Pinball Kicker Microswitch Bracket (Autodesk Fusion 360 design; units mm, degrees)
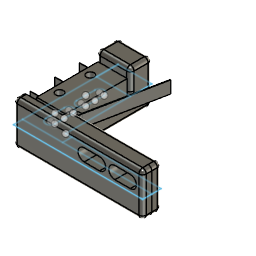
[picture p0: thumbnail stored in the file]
sketch "Microswitch" plane through (0, 0, 0) normal (0, 0, 1) x axis (1, 0, 0)
  line L1 (-2.5, -5) -> (7, -5)
  line L2 (-2.5, 15) -> (-2.5, -5)
  line L3 (7, 15) -> (-2.5, 15)
  line L4 (13, 23) -> (8.2, -1)
  line L5 (-6.5, -3) -> (-2.5, -3)
  line L6 (-6.5, 13) -> (-2.5, 13)
  line L7 (-6.5, 5) -> (-2.5, 5)
  line L8 (13.2, 23) -> (8.2, -2)
  line L9 (13.2, 23) -> (13, 23)
  line L10 (8.2, -2) -> (8, -2)
  line L11 (-6.5, -3.1) -> (-2.5, -3.1)
  line L12 (-6.5, 4.9) -> (-2.5, 4.9)
  line L13 (-6.5, 12.9) -> (-2.5, 12.9)
  line L14 (-6.5, 12.9) -> (-6.5, 13)
  line L15 (-6.5, 4.9) -> (-6.5, 5)
  line L16 (-6.5, -3.1) -> (-6.5, -3)
  line L17 (7, -5) -> (7, 15)
  line L18 (8.2, -1) -> (7, -1)
  line L19 (7, -2) -> (8.2, -2)
  circle C1 centre (0, 0) radius 1.25
  circle C2 centre (0, 10) radius 1.25
  point P1 (0, 0)
  point P2 (0, 0)
  point P8 (-2.5, -3)
  point P10 (-2.5, 13)
  point P12 (-2.5, 5)
  point P24 (7, -1)
  point P26 (7, -2)
  coincident P1 P2
  horizontal L1
  perpendicular L1 L2
  perpendicular L2 L3
  coincident L2 P8
  perpendicular L2 L5
  coincident L2 P10
  perpendicular L2 L6
  midpoint L2 P12
  perpendicular L2 L7
  horizontal L9
  perpendicular L13 L14
  perpendicular L12 L15
  perpendicular L11 L16
  coincident L17 P24
  coincident L17 P26
  perpendicular L17 L19
extrude "Extrude1" new body sketch "Microswitch" profile of C1 C2 L1 L2 L3 along normal blind 6.5 bodies "Microswitch"
extrude "Extrude3" add sketch "Microswitch" profile of L2 L5 L6 L7 L11 L12 L13 L14 L15 L16 blind 4 from offset 1.25
sketch "Game Deck Geometry" plane through (0, 0, 0) normal (0, 0, 1) x axis (1, 0, 0)
  line L1 (38, 5) -> (11, 5)
  line L2 (38, -4) -> (15, -4)
  line L3 (11, -4) -> (11, 5)
  line L4 (15, -4) -> (11, -4)
  line L5 (38, 5) -> (38, -4)
  circle C1 centre (14, 18) radius 2
  horizontal L1
  horizontal L2
  perpendicular L1 L3
  perpendicular L1 L5
  dimension "d10" diameter C1 = 4
sketch "Bracket" plane through (0, 0, 0) normal (0, 0, 1) x axis (1, 0, 0)
  line L1 (8, -4) -> (8, 24)
  line L2 (39, -4) -> (8, -4)
  line L3 (39, -7) -> (39, -4)
  line L4 (-3, -7) -> (39, -7)
  line L5 (-3, 24) -> (-3, -7)
  line L6 (8, 24) -> (-3, 24)
  line L7 (-3, 17) -> (-3, 24)
  line L8 (8, 17) -> (-3, 17)
  line L9 (0.5, 13) -> (0.5, 10)
  line L10 (3.5, 13) -> (3.5, 10)
  line L11 (3.5, 10) -> (3.5, 7)
  line L12 (0.5, 10) -> (0.5, 7)
  line L13 (0.5, 3) -> (0.5, 0)
  line L14 (3.5, 3) -> (3.5, 0)
  line L15 (3.5, 0) -> (3.5, -3)
  line L16 (0.5, 0) -> (0.5, -3)
  line L17 (10, -7) -> (10, -4)
  line L18 (-3, -10) -> (-3, -7)
  line L19 (39, -10) -> (-3, -10)
  line L20 (39, -7) -> (39, -10)
  arc A1 centre (2, 13) radius 1.5 clockwise from (0.5, 13) to (3.5, 13)
  arc A2 centre (2, 7) radius 1.5 clockwise from (3.5, 7) to (0.5, 7)
  arc A3 centre (2, 3) radius 1.5 clockwise from (0.5, 3) to (3.5, 3)
  arc A4 centre (2, -3) radius 1.5 clockwise from (3.5, -3) to (0.5, -3)
  point P9 (-3, 24)
  point P11 (8, 17)
  point P36 (10, -4)
  point P37 (10, -7)
  point P40 (39, -7)
  perpendicular L2 L3
  perpendicular L3 L4
  perpendicular L4 L5
  perpendicular L1 L6
  coincident L6 P9
  perpendicular L6 L7
  coincident L1 P11
  perpendicular L1 L8
  vertical L9
  vertical L10
  vertical L12
  vertical L11
  vertical L13
  vertical L14
  vertical L16
  vertical L15
  coincident L2 P36
  coincident L4 P37
  perpendicular L4 L17
  perpendicular L4 L18
  perpendicular L18 L19
  coincident L4 P40
extrude "Extrude4" new body sketch "Bracket" blind -6 from offset -0.3
extrude "Extrude6" add sketch "Bracket" profile of L1 L2 L3 L4 L5 L6 L7 L8 L17 L18 L19 L20 blind 8 from offset -0.3
sketch "Bracket Drill" plane through (0, -4, 0) normal (0, 1, 0) x axis (-1, 0, 0)
  line L1 (-25, 5) -> (-20, 5)
  line L2 (-25, 1) -> (-20, 1)
  line L3 (-35, 1) -> (-30, 1)
  line L4 (-35, 5) -> (-30, 5)
  arc A1 centre (-20, 3) radius 2 clockwise from (-20, 5) to (-20, 1)
  arc A2 centre (-25, 3) radius 2 clockwise from (-25, 1) to (-25, 5)
  arc A3 centre (-30, 3) radius 2 clockwise from (-30, 5) to (-30, 1)
  arc A4 centre (-35, 3) radius 2 clockwise from (-35, 1) to (-35, 5)
  horizontal L1
  horizontal L2
  horizontal L4
  horizontal L3
extrude "Extrude7" new body sketch "Game Deck Geometry" along normal blind 20 and against normal blind 20 bodies "Rope", "Base"
extrude "Extrude8" cut sketch "Bracket Drill" against normal blind 10
fillet "Fillet3" radius 0.5
move "Move1"
fillet "Fillet4" radius 1.2
fillet "Fillet5" radius 1.2
fillet "Fillet6" radius 1.2
fillet "Fillet7" radius 1.2
fillet "Fillet8" radius 1.2
move "Move2"
extrude "Extrude9" add sketch "Microswitch" profile of L4 L8 L9 L10 L17 L18 L19 blind 4 from offset 1.25
move "Move3"
named bodies: "Microswitch", "Bracket", "Rope", "Base"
